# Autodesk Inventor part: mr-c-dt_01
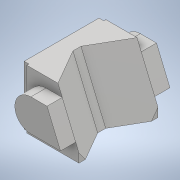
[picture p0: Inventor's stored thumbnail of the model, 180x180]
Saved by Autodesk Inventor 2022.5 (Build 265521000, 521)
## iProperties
Part Number: mr-c-dt_01
Material: 一般
Document SubType Name: Modeling
Designer: ImaoCorp
Density: 1 g/cm^3
Appearance: 既定
Author: ImaoCorp
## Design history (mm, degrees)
feature "mr-c-dt_01"
node "ソリッド1"
